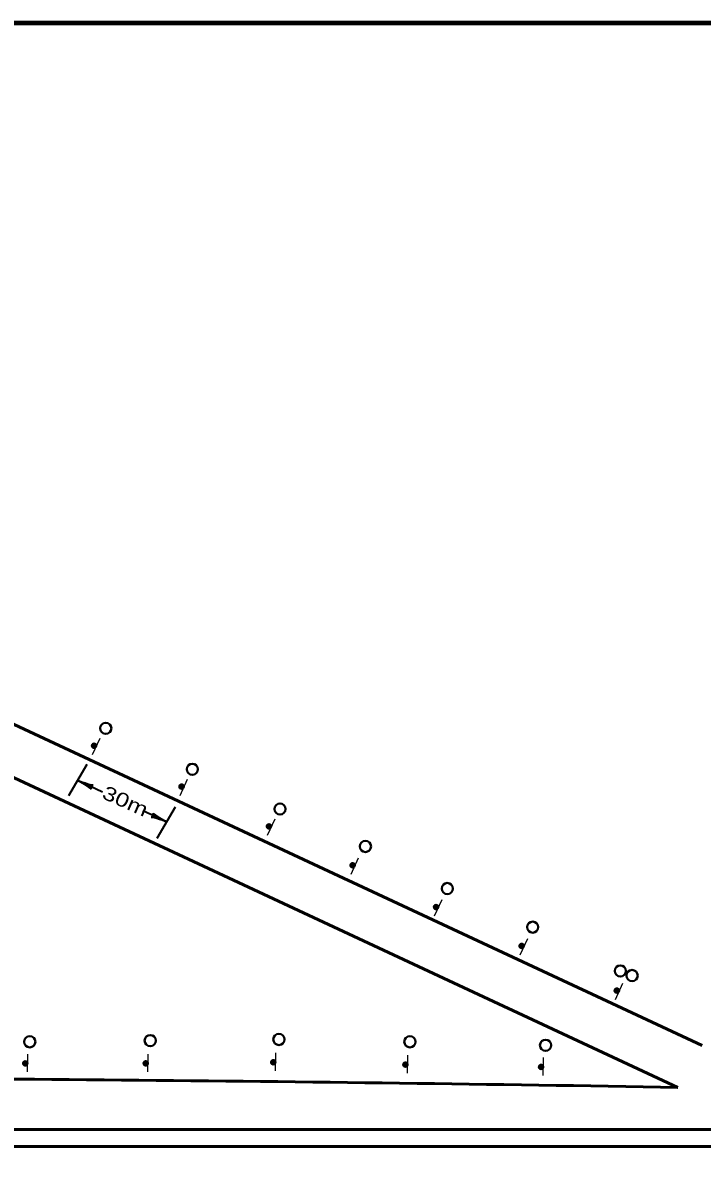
# Model space of a CAD drawing. Extents: x 393 to 1249, y -102 to 530.
# Drawn here: x 962.8 to 1080.9, y 325.7 to 523.2 of the extents above; entities that cross this region are included whole.
import ezdxf
from ezdxf.enums import TextEntityAlignment as Align

# ---------------------------------------------------------------- set-up
doc = ezdxf.new("R2010")
doc.units = 0
doc.header["$LTSCALE"] = 0.97
doc.layers.add('1', color=7, linetype='Continuous', lineweight=40)
doc.layers.add('4', color=7, linetype='Continuous', lineweight=25)

msp = doc.modelspace()

# ---------------------------------------------------------------- linework, layer by layer
at = {"layer": '1', "lineweight": 53}
for p, q in [((1080.9208, 345.4442), (918.2161, 421.3147)), ((1076.6773, 338.1447), (912.6644, 414.6252)), ((955.6366, 327.898), (1163.6445, 327.898))]:
    msp.add_line(p, q, dxfattribs=at)
at = {"layer": '1', "lineweight": 35}
for p, q in [((970.8312, 388.868), (973.99, 394.3397)), ((976.6921, 389.4867), (972.3557, 391.5088)), ((987.8253, 384.2951), (983.6939, 386.2216)), ((986.1812, 381.4471), (989.34, 386.9189))]:
    msp.add_line(p, q, dxfattribs=at)
at = {"layer": '1', "lineweight": 158}
msp.add_lwpolyline([(1242.1684, 523.2155), (450.4684, 523.1155), (450.5684, -2.8845)], dxfattribs=at)
at = {"layer": '1', "lineweight": 53}
msp.add_lwpolyline([(882.3469, 330.814), (955.6366, 330.814), (1163.6445, 330.814)], dxfattribs=at)
at = {"layer": '1'}
for centre, radius in [((977.2329, 400.5621), 0.972), ((975.2001, 397.5263), 0.3791), ((975.1907, 397.5521), 0.3402), ((975.2048, 397.5133), 0.35), ((975.196, 397.5175), 0.3305), ((975.2001, 397.5263), 0.3013), ((975.2001, 397.5263), 0.2819), ((975.196, 397.5175), 0.2722), ((975.196, 397.5175), 0.2527), ((975.1872, 397.5216), 0.2335), ((975.1784, 397.5257), 0.2138), ((975.135, 397.5245), 0.1555), ((975.1784, 397.5257), 0.1944), ((975.1303, 397.5374), 0.1461), ((975.1608, 397.5339), 0.175), ((975.1173, 397.5327), 0.1166), ((975.1085, 397.5368), 0.0977), ((975.0997, 397.5409), 0.0778), ((975.0821, 397.5491), 0.0583), ((975.0645, 397.5573), 0.0389), ((975.0469, 397.5656), 0.0194), ((975.1878, 397.4998), 0.1555), ((975.1919, 397.5086), 0.1069), ((975.2224, 397.666), 0.00972), ((992.2777, 393.4463), 0.972), ((990.4017, 390.4322), 0.3791), ((990.3923, 390.458), 0.3402), ((990.4064, 390.4193), 0.35), ((990.3975, 390.4234), 0.3305), ((990.4017, 390.4322), 0.3013), ((990.4017, 390.4322), 0.2819), ((990.3975, 390.4234), 0.2722), ((990.3975, 390.4234), 0.2527), ((990.3887, 390.4275), 0.2335), ((990.3799, 390.4316), 0.2138), ((990.3365, 390.4304), 0.1555), ((990.3799, 390.4316), 0.1944), ((990.3318, 390.4433), 0.1461), ((990.3623, 390.4398), 0.175), ((990.3189, 390.4386), 0.1166), ((990.3101, 390.4427), 0.0977), ((990.3012, 390.4469), 0.0778), ((990.2836, 390.4551), 0.0583), ((990.266, 390.4633), 0.0389), ((990.2484, 390.4715), 0.0194), ((990.3893, 390.4058), 0.1555), ((990.3934, 390.4146), 0.1069), ((990.4239, 390.572), 0.00972), ((1007.5258, 386.5339), 0.972), ((1005.6031, 383.5071), 0.3791), ((1005.5937, 383.5329), 0.3402), ((1005.6078, 383.4942), 0.35), ((1005.599, 383.4983), 0.3305), ((1005.6031, 383.5071), 0.3013), ((1005.6031, 383.5071), 0.2819), ((1005.599, 383.4983), 0.2722), ((1005.599, 383.4983), 0.2527), ((1005.5902, 383.5024), 0.2335), ((1005.5814, 383.5065), 0.2138), ((1005.5379, 383.5053), 0.1555), ((1005.5814, 383.5065), 0.1944), ((1005.5332, 383.5182), 0.1461), ((1005.5637, 383.5147), 0.175), ((1005.5203, 383.5135), 0.1166), ((1005.5115, 383.5176), 0.0977), ((1005.5027, 383.5218), 0.0778), ((1005.4851, 383.53), 0.0583), ((1005.4674, 383.5382), 0.0389), ((1005.4498, 383.5464), 0.0194), ((1005.5908, 383.4807), 0.1555), ((1005.5949, 383.4895), 0.1069), ((1005.6254, 383.6469), 0.00972), ((1022.3673, 380.028), 0.972), ((1020.1289, 376.7509), 0.3791), ((1020.1195, 376.7767), 0.3402), ((1020.1336, 376.738), 0.35), ((1020.1248, 376.7421), 0.3305), ((1020.1289, 376.7509), 0.3013), ((1020.1289, 376.7509), 0.2819), ((1020.1248, 376.7421), 0.2722), ((1020.1248, 376.7421), 0.2527), ((1020.116, 376.7462), 0.2335), ((1020.1072, 376.7503), 0.2138), ((1020.0637, 376.7491), 0.1555), ((1020.1072, 376.7503), 0.1944), ((1020.059, 376.762), 0.1461), ((1020.0896, 376.7585), 0.175), ((1020.0461, 376.7573), 0.1166), ((1020.0373, 376.7614), 0.0977), ((1020.0285, 376.7655), 0.0778), ((1020.0109, 376.7738), 0.0583), ((1019.9932, 376.782), 0.0389), ((1019.9756, 376.7902), 0.0194), ((1020.1166, 376.7245), 0.1555), ((1020.1207, 376.7333), 0.1069), ((1020.1512, 376.8907), 0.00972), ((1036.5988, 372.709), 0.972), ((1034.6548, 369.488), 0.3791), ((1034.6454, 369.5139), 0.3402), ((1034.6595, 369.4751), 0.35), ((1034.6507, 369.4792), 0.3305), ((1034.6548, 369.488), 0.3013), ((1034.6548, 369.488), 0.2819), ((1034.6507, 369.4792), 0.2722), ((1034.6507, 369.4792), 0.2527), ((1034.6419, 369.4833), 0.2335), ((1034.6331, 369.4874), 0.2138), ((1034.5896, 369.4862), 0.1555), ((1034.6331, 369.4874), 0.1944), ((1034.5849, 369.4992), 0.1461), ((1034.6154, 369.4957), 0.175), ((1034.572, 369.4945), 0.1166), ((1034.5632, 369.4986), 0.0977), ((1034.5544, 369.5027), 0.0778), ((1034.5368, 369.5109), 0.0583), ((1034.5191, 369.5191), 0.0389), ((1034.5015, 369.5273), 0.0194), ((1034.6425, 369.4616), 0.1555), ((1034.6466, 369.4704), 0.1069), ((1034.6771, 369.6278), 0.00972), ((1051.4403, 365.9998), 0.972), ((1049.5184, 362.7317), 0.3791), ((1049.509, 362.7576), 0.3402), ((1049.5231, 362.7188), 0.35), ((1049.5143, 362.7229), 0.3305), ((1049.5184, 362.7317), 0.3013), ((1049.5184, 362.7317), 0.2819), ((1049.5143, 362.7229), 0.2722), ((1049.5143, 362.7229), 0.2527), ((1049.5055, 362.727), 0.2335), ((1049.4966, 362.7311), 0.2138), ((1049.4532, 362.73), 0.1555), ((1049.4966, 362.7311), 0.1944), ((1049.4485, 362.7429), 0.1461), ((1049.479, 362.7394), 0.175), ((1049.4356, 362.7382), 0.1166), ((1049.4268, 362.7423), 0.0977), ((1049.418, 362.7464), 0.0778), ((1049.4003, 362.7546), 0.0583), ((1049.3827, 362.7628), 0.0389), ((1049.3651, 362.771), 0.0194), ((1049.506, 362.7053), 0.1555), ((1049.5102, 362.7141), 0.1069), ((1049.5406, 362.8715), 0.00972), ((1066.6759, 358.3883), 0.972), ((1068.7246, 357.5892), 0.972), ((1066.0711, 354.9621), 0.3791), ((1066.0617, 354.988), 0.3402), ((1066.0758, 354.9492), 0.35), ((1066.067, 354.9533), 0.3305), ((1066.0711, 354.9621), 0.3013), ((1066.0711, 354.9621), 0.2819), ((1066.067, 354.9533), 0.2722), ((1066.067, 354.9533), 0.2527), ((1066.0582, 354.9574), 0.2335), ((1066.0494, 354.9615), 0.2138), ((1066.0059, 354.9604), 0.1555), ((1066.0494, 354.9615), 0.1944), ((1066.0012, 354.9733), 0.1461), ((1066.0318, 354.9698), 0.175), ((1065.9883, 354.9686), 0.1166), ((1065.9795, 354.9727), 0.0977), ((1065.9707, 354.9768), 0.0778), ((1065.9531, 354.985), 0.0583), ((1065.9355, 354.9932), 0.0389), ((1065.9179, 355.0014), 0.0194), ((1066.0588, 354.9357), 0.1555), ((1066.0629, 354.9445), 0.1069), ((1066.0934, 355.1019), 0.00972), ((964.018, 346.0757), 0.972), ((984.9586, 346.279), 0.972), ((1007.3225, 346.4823), 0.972), ((1030.093, 346.0757), 0.972), ((1053.6767, 345.4658), 0.972), ((963.2411, 342.3193), 0.3791), ((963.222, 342.339), 0.3402), ((963.2506, 342.3094), 0.35), ((963.2409, 342.3095), 0.3305), ((963.2411, 342.3193), 0.3013), ((963.2411, 342.3193), 0.2819), ((963.2409, 342.3095), 0.2722), ((963.2409, 342.3095), 0.2527), ((963.2312, 342.3097), 0.2335), ((963.2215, 342.3099), 0.2138), ((963.1727, 342.301), 0.1461), ((963.1823, 342.2911), 0.1555), ((963.202, 342.3102), 0.175), ((963.2215, 342.3099), 0.1944), ((963.1628, 342.2915), 0.1166), ((963.1531, 342.2916), 0.0977), ((963.1434, 342.2918), 0.0778), ((963.1239, 342.2921), 0.0583), ((963.1045, 342.2925), 0.0389), ((963.0851, 342.2928), 0.0194), ((963.2406, 342.2901), 0.1555), ((963.2407, 342.2998), 0.1069), ((963.2046, 342.456), 0.00972), ((984.1818, 342.3193), 0.3791), ((984.1627, 342.339), 0.3402), ((984.1913, 342.3094), 0.35), ((984.1816, 342.3095), 0.3305), ((984.1818, 342.3193), 0.3013), ((984.1818, 342.3193), 0.2819), ((984.1816, 342.3095), 0.2722), ((984.1816, 342.3095), 0.2527), ((984.1719, 342.3097), 0.2335), ((984.1622, 342.3099), 0.2138), ((984.1134, 342.301), 0.1461), ((984.1229, 342.2911), 0.1555), ((984.1427, 342.3102), 0.175), ((984.1622, 342.3099), 0.1944), ((984.1035, 342.2915), 0.1166), ((984.0938, 342.2916), 0.0977), ((984.0841, 342.2918), 0.0778), ((984.0646, 342.2921), 0.0583), ((984.0452, 342.2925), 0.0389), ((984.0258, 342.2928), 0.0194), ((984.1813, 342.2901), 0.1555), ((984.1814, 342.2998), 0.1069), ((984.1453, 342.456), 0.00972), ((1006.3422, 342.5226), 0.3791), ((1006.3231, 342.5423), 0.3402), ((1006.3518, 342.5127), 0.35), ((1006.3421, 342.5128), 0.3305), ((1006.3422, 342.5226), 0.3013), ((1006.3422, 342.5226), 0.2819), ((1006.3421, 342.5128), 0.2722), ((1006.3421, 342.5128), 0.2527), ((1006.3323, 342.513), 0.2335), ((1006.3226, 342.5132), 0.2138), ((1006.2739, 342.5043), 0.1461), ((1006.2834, 342.4944), 0.1555), ((1006.3226, 342.5132), 0.1944), ((1006.3032, 342.5135), 0.175), ((1006.264, 342.4948), 0.1166), ((1006.2543, 342.4949), 0.0977), ((1006.2445, 342.4951), 0.0778), ((1006.2251, 342.4954), 0.0583), ((1006.2057, 342.4958), 0.0389), ((1006.1862, 342.4961), 0.0194), ((1006.3417, 342.4934), 0.1555), ((1006.3419, 342.5031), 0.1069), ((1006.3057, 342.6593), 0.00972), ((1029.316, 342.1159), 0.3791), ((1029.2969, 342.1357), 0.3402), ((1029.3256, 342.1061), 0.35), ((1029.3158, 342.1062), 0.3305), ((1029.316, 342.1159), 0.3013), ((1029.316, 342.1159), 0.2819), ((1029.3158, 342.1062), 0.2722), ((1029.3158, 342.1062), 0.2527), ((1029.3061, 342.1064), 0.2335), ((1029.2964, 342.1066), 0.2138), ((1029.2477, 342.0977), 0.1461), ((1029.2572, 342.0878), 0.1555), ((1029.2964, 342.1066), 0.1944), ((1029.277, 342.1069), 0.175), ((1029.2378, 342.0881), 0.1166), ((1029.228, 342.0883), 0.0977), ((1029.2183, 342.0885), 0.0778), ((1029.1989, 342.0888), 0.0583), ((1029.1795, 342.0892), 0.0389), ((1029.16, 342.0895), 0.0194), ((1029.3155, 342.0868), 0.1555), ((1029.3157, 342.0965), 0.1069), ((1029.2795, 342.2527), 0.00972), ((1052.8997, 341.7093), 0.3791), ((1052.8806, 341.7291), 0.3402), ((1052.9093, 341.6994), 0.35), ((1052.8996, 341.6996), 0.3305), ((1052.8997, 341.7093), 0.3013), ((1052.8997, 341.7093), 0.2819), ((1052.8996, 341.6996), 0.2722), ((1052.8996, 341.6996), 0.2527), ((1052.8898, 341.6998), 0.2335), ((1052.8801, 341.6999), 0.2138), ((1052.8314, 341.6911), 0.1461), ((1052.8409, 341.6812), 0.1555), ((1052.8801, 341.6999), 0.1944), ((1052.8607, 341.7003), 0.175), ((1052.8215, 341.6815), 0.1166), ((1052.8992, 341.6802), 0.1555), ((1052.8994, 341.6899), 0.1069), ((1052.8632, 341.8461), 0.00972), ((1052.8118, 341.6817), 0.0977), ((1052.802, 341.6819), 0.0778), ((1052.7826, 341.6822), 0.0583), ((1052.7632, 341.6825), 0.0389), ((1052.7437, 341.6829), 0.0194)]:
    msp.add_circle(centre, radius, dxfattribs=at)
at = {"layer": '1', "lineweight": 53}
msp.add_arc((877.2802, -11096.4711), 11436.3542, 89.00098, 89.97023, dxfattribs=at)
at = {"layer": '1'}
for centre, major_axis, ratio, start_param, end_param in [((973.2558, 390.8621), (1.4752, -0.8763), 0.07063, 6.28230741, 8.55970261), ((973.4305, 391.3039), (-1.6372, 0.596), 0.122415, 0.89635335, 3.14159265), ((986.9251, 384.9418), (-1.4752, 0.8763), 0.07063, 6.28230741, 8.55970261), ((986.7505, 384.5), (1.6372, -0.596), 0.122415, 0.89635335, 3.14159265)]:
    msp.add_ellipse(centre, major_axis=major_axis, ratio=ratio, start_param=start_param, end_param=end_param, dxfattribs=at)
at = {"layer": '4'}
for p, q in [((974.9417, 396.0059), (976.2562, 398.825)), ((990.1432, 388.9119), (991.4578, 391.7309)), ((1005.3446, 381.9868), (1006.6592, 384.8058)), ((1019.8704, 375.2306), (1021.185, 378.0496)), ((1034.3963, 367.9677), (1035.7109, 370.7867)), ((1049.2599, 361.2114), (1050.5745, 364.0304)), ((1065.8127, 353.4418), (1067.1273, 356.2608)), ((963.6233, 340.8254), (963.6778, 343.9352)), ((984.5641, 340.8254), (984.6184, 343.9352)), ((1006.7245, 341.0287), (1006.7789, 344.1385)), ((1029.6982, 340.6221), (1029.7527, 343.7319)), ((1053.282, 340.2154), (1053.3364, 343.3253))]:
    msp.add_line(p, q, dxfattribs=at)
for centre in [(975.2043, 397.5351), (990.4058, 390.441), (1005.6072, 383.5159), (1020.133, 376.7597), (1034.6589, 369.4968), (1049.5225, 362.7405), (1066.0752, 354.9709), (963.2412, 342.329), (984.1819, 342.329), (1006.3424, 342.5323), (1029.3162, 342.1257), (1052.8999, 341.719)]:
    msp.add_circle(centre, 0.3985, dxfattribs=at)

# ---------------------------------------------------------------- texts
at = {"layer": '1', "width": 1.3}
msp.add_text('30m', height=2.43, rotation=336, dxfattribs=at).set_placement((980.153, 386.8055), align=Align.CENTER)

doc.saveas('drawing.dxf')
